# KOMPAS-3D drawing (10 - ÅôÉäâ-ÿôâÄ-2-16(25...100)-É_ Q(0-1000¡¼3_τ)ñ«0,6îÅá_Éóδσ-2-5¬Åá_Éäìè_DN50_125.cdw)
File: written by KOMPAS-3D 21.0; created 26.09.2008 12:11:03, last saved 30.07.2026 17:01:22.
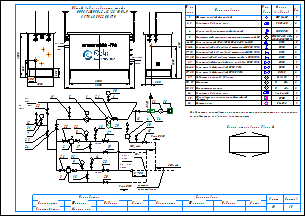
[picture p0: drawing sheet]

Sheets 1-2: A3, landscape

Document properties: Наименование: Макро:21; Автор: RaskoAdmin; Форматы листов документа: 2xA3; Полное имя файла: \\UR38nt01\Departments\КТО\КБ ПУРДГ\Заявки\Прайс-лист на типовые шкафы ГРПШ\ПУРДГ_стандарт_30_04_2026\ПУРДГ с РДНК\ПУРДГ-ШУГО-2-16(25...100)-Р_ Q(0-1000нм3_ч)до0,6МПа_Рвых-2-5кПа_РДНК_DN50_125.cdw

Title block, sheet 1: Наименование: Пункт учета газа / ПУГ-Ш-400-Р / ЛГТИ.485922.001ТУ; designation: ЛГТИ.03.4411141; sheet number: 1; Количество листов документа: 2; organisation: ООО "ЭЛЬСТЕР Газэлектроника"; Форматы листов документа: A3; stored path: C:\Рабочие документы\Компас\ПУГ\Схема.cdw; Разработал: Устинов; Проверил: Кошкин; Утвердил: Кошкин
Title block, sheet 2: sheet number: 2; stored path: D:\Рабочие документы\Заявки\ПУРДГ\ПУРДГ-ШУЭО-2-100-Р 4411220.cdw; designation, second copy: ЛГТИ.03.4411141-

Views: Вид 1, Вид 2
Referenced files: wcvoit.frw
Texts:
  Normal
  Общий вид и габариты шкафа
  ПУРДГ-ШУГО-2-16(25...100)-Р
  DN125
  Выход газа
  DN50
  Вход газа
  logo-rasko-ge.png
  DN 1
  местное
  сопротивление
  Римп DN15
  Римп DN20
  Выход
  газа
  Р=     кПа
  Вход
  Р=       МПа
  PDI
  № на
  схеме
  Усл.
  обозн.
  Марка
  (модель)
  Кол.
  Фильтр газовый фланцевый
  ФГ 16-50
  Регулятор давления газа
  РДНК-50
  Клапан предохранительный сбросной
  КПС DN20
  Измерительный комплекс с ротационным счетчиком Ду50
  СГ-ЭК-Р-(0,2...2,0)-
  Кран кнопочный VE-РАСКО-НЗ-1,6-G1/2-М20
  DN15
  Кран шаровой "под приварку" штуцерный DN20 PN16
  DN20
  Кран шаровой "под приварку" штуцерный DN15 PN16
  Кран шаровой "под приварку" штуцерный п/п DN15 PN16
  Кран шаровой фланцевый с мех. приводом DN50 PN16
  Кран шаровой фланцевый DN50 PN16
  Кран шаровой фланцевый DN125 PN16
  Индикатор перепада давления
  Манометр
  Манометр-напоромер
  Обогреватель газогорелочный шкафной
  (Эльтон")
  Счетчик газа
  Delta 15
  0...     МПа
  0...     кПа
  Venio-A-15
  ОГШН
  BK-G1,6
  Схема открывания дверей
  Предприятие изготовитель может заменять комплектующие на аналогичные,
  не ухудшающие заявленных характеристик.
  Должность
  Конструктор
  Фамилия
  Подпись
  Дата
  Согласовано
  Максимкин
  Лист
  Листов
  POLYLINE_STYLE_0.18_RGB_0_0_0
  POLYLINE_STYLE_0.50_RGB_0_0_0
  POLYLINE_STYLE_0.34_RGB_0_0_0
  PHANTOM_RGB_0_0_0_SC_1_THICK_0.18
  K5LT_THIN_RGB_0_0_0_THICK_0.18
  K5LT32769_RGB_0_0_0_THICK_0.18
  K5LT12_RGB_0_0_0_SC_1_THICK_0.18
  K5LT_DASHED_RGB_0_0_0_SC_1_THICK_0.18
  ACISOTGL_RGB_0_0_0_SC_0.8_THICK_0.25
  CONTINUOUS_RGB_0_127_31_THICK_0.3
  CONTINUOUS_RGB_0_0_255_THICK_0.35
  CONTINUOUS_RGB_255_0_0_THICK_0.35
  POLYLINE_STYLE_0.25_RGB_0_0_0
  CONTINUOUS_RGB_0_0_0_THICK_0.5
  POLYLINE_STYLE_0.35_RGB_0_0_255
  CONTINUOUS_RGB_0_0_0_THICK_0.4
  CONTINUOUS_RGB_0_0_0_THICK_0.35
  НЕВИДИМАЯ_RGB_0_0_0_SC_0.3_THICK_0.25
  СONTINUOUS_RGB_0_0_0_THICK_0.25
  ОСЕВАЯ2_RGB_248_153_30_SC_0.3_THICK_0.25
  Без оформления
Dimensions and other numbers on the sheet: 1; 1500; 250; 300; 1050; 550; 305; 2500; 4130; 2000; 2800; 5,,,7DN 1; 7; 31; 12; 22; 23; 24; 11; 5; 21; 6; 30; 25; 32; 8; 2; 17; 13; 27; 19; 4; 10; 15; 26; 33; 9; 3; 18; 14; 28; 20; 29; 2, 3; 6-10; 11-16; 17, 18; 19, 20; 22-26; 27, 28; 30, 31; 32, 33; 34; 35; 36; 16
